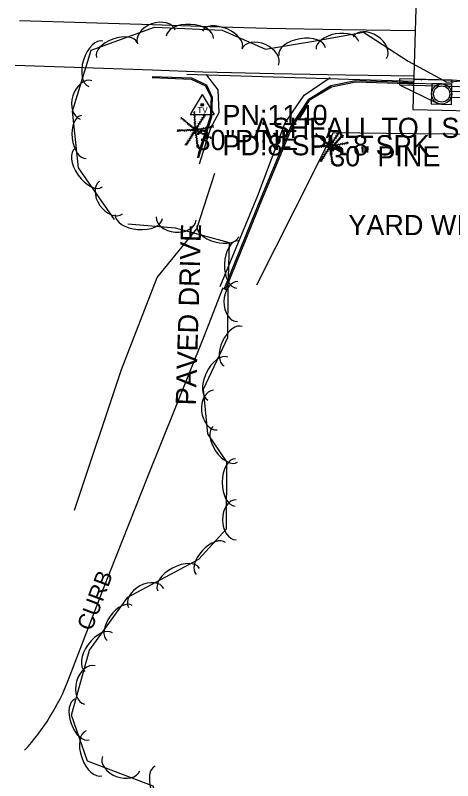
# Model space of a CAD drawing. Extents: x 978516 to 993312, y 1836504 to 1846212.
# Drawn here: x 992339 to 992447.3, y 1840498 to 1840687.6 of the extents above; entities that cross this region are included whole.
import ezdxf

# ---------------------------------------------------------------- set-up
doc = ezdxf.new("R2010")
doc.units = 0
for name, color, linetype in [('R_Drainage', 7, 'Continuous'), ('R_Proposed Road', 7, 'Continuous'), ('S_CURB', 7, 'Continuous'), ('S_CURB_ANNOT', 7, 'Continuous'), ('S_DRIVEWAY', 7, 'Continuous'), ('S_DRIVEWAY_ANNOT', 7, 'Continuous'), ('S_EDGE_PAVEMENT', 7, 'Continuous'), ('S_PARKING', 7, 'Continuous'), ('S_PAVEMENT_CROWN', 7, 'Continuous'), ('S_SECONDARY_CTL', 7, 'Continuous'), ('S_SECONDARY_CTL_ANNOT', 7, 'Continuous'), ('S_SURVEY_TEXT_ANNOT', 7, 'Continuous'), ('S_TREE', 7, 'Continuous'), ('S_TREE_ANNOT', 7, 'Continuous')]:
    doc.layers.add(name, color=color, linetype=linetype)

msp = doc.modelspace()

# ---------------------------------------------------------------- linework, layer by layer
at = {"layer": 'R_Drainage'}
for p, q in [((992434.08, 1840670.38), (992443.43, 1840665.84)), ((992434.1, 1840670.88), (992447.09, 1840670.52)), ((992446.4, 1840668.79), (992530.67, 1840666.48)), ((992446.36, 1840667.29), (992530.63, 1840664.99)), ((992441.96, 1840665.66), (992446.96, 1840665.52))]:
    msp.add_line(p, q, dxfattribs=at)
for points in [[(992434.08, 1840670.38), (992447.08, 1840670.02), (992447.12, 1840671.52), (992434.12, 1840671.88)], [(992441.96, 1840665.66), (992446.96, 1840665.52), (992447.09, 1840670.52), (992442.09, 1840670.66)]]:
    msp.add_lwpolyline(points, close=True, dxfattribs=at)
for radius in [2.5, 2.5, 2.5, 2, 2, 2]:
    msp.add_circle((992444.53, 1840668.09), radius, dxfattribs=at)
at = {"layer": 'R_Proposed Road'}
for p, q in [((992438.54, 1840704.81), (992437.43, 1840664.28)), ((992437.59, 1840670.28), (992673.06, 1840663.85)), ((992437.63, 1840671.78), (992673.1, 1840665.35)), ((992437.43, 1840664.28), (992619.94, 1840659.29))]:
    msp.add_line(p, q, dxfattribs=at)
at = {"layer": 'S_CURB'}
for points in [[(992372.87, 1840672.14), (992382.52, 1840671.78), (992386.08, 1840670.11), (992387.44, 1840667.24), (992387.22, 1840662.39), (992384.35, 1840653.51), (992384.09, 1840652.31)], [(992372.88, 1840672.44), (992382.59, 1840672.08), (992386.3, 1840670.34), (992387.74, 1840667.31), (992387.52, 1840662.34), (992384.64, 1840653.44), (992384.38, 1840652.24)], [(992437.61, 1840670.88), (992436.21, 1840670.93), (992423.24, 1840671.35), (992417.14, 1840670.09), (992411.51, 1840666.66), (992407.23, 1840660.12), (992399.97, 1840642.66), (992390.64, 1840619.62)], [(992437.6, 1840670.58), (992436.2, 1840670.63), (992423.27, 1840671.05), (992417.25, 1840669.81), (992411.72, 1840666.44), (992407.49, 1840659.98), (992400.25, 1840642.54), (992390.92, 1840619.5)]]:
    msp.add_lwpolyline(points, dxfattribs=at)
at = {"layer": 'S_DRIVEWAY'}
for points in [[(992384.59, 1840650.82), (992387.38, 1840659.73), (992389.49, 1840663.5), (992389.21, 1840669.14), (992386.43, 1840672.74)], [(992389.72, 1840620.38), (992399.02, 1840642.94), (992405.76, 1840660.91), (992410.54, 1840667.8), (992416.9, 1840672.15)]]:
    msp.add_lwpolyline(points, dxfattribs=at)
at = {"layer": 'S_EDGE_PAVEMENT'}
for points in [[(992339, 1840675.26), (992355.97, 1840674.67), (992372.95, 1840674.08), (992385.44, 1840673.55), (992403.08, 1840673.17), (992420.71, 1840672.8), (992437.65, 1840672.55)], [(992381.49, 1840672.98), (992437.62, 1840671.3)]]:
    msp.add_lwpolyline(points, dxfattribs=at)
at = {"layer": 'S_PARKING'}
for points in [[(992353.64, 1840564.98), (992365.32, 1840599.8), (992374.07, 1840622.61), (992383.91, 1840634.69), (992388.41, 1840648.48)], [(992352.18, 1840523.01), (992360.81, 1840545.57), (992371.83, 1840573.37), (992385.7, 1840607.87), (992390.48, 1840620.12)]]:
    msp.add_lwpolyline(points, dxfattribs=at)
msp.add_ellipse((992301.38, 1840541.99), major_axis=(35.02, 43.34), ratio=0.97052, start_param=4.653541, end_param=5.025621, dxfattribs=at)
at = {"layer": 'S_PAVEMENT_CROWN'}
msp.add_lwpolyline([(992340.02, 1840686.27), (992356.48, 1840685.77), (992372.94, 1840685.27), (992387.13, 1840684.83), (992401.32, 1840684.39), (992419.74, 1840684.1), (992437.96, 1840683.81)], dxfattribs=at)
at = {"layer": 'S_SECONDARY_CTL'}
for p, q in [((992385.27, 1840668), (992382.26, 1840663.04)), ((992385.27, 1840668), (992388.21, 1840663.04)), ((992382.26, 1840663.04), (992388.21, 1840663.04))]:
    msp.add_line(p, q, dxfattribs=at)
for radius in [0.311, 0.183, 0.103]:
    msp.add_circle((992385.27, 1840665.39), radius, dxfattribs=at)
at = {"layer": 'S_TREE'}
for p, q in [((992383.33, 1840663.27), (992383.11, 1840663.47)), ((992383.36, 1840662.71), (992383.14, 1840662.91)), ((992383.59, 1840659.19), (992383.32, 1840663.63)), ((992383.33, 1840663.52), (992383.52, 1840663.75)), ((992383.36, 1840663.04), (992383.55, 1840663.28)), ((992383.39, 1840662.44), (992383.58, 1840662.68)), ((992383.59, 1840659.19), (992385.93, 1840662.88)), ((992385.66, 1840662.5), (992385.57, 1840662.79)), ((992385.79, 1840662.66), (992386.09, 1840662.71)), ((992385.9, 1840662.84), (992385.81, 1840663.13)), ((992380.3, 1840661.94), (992380.01, 1840661.89)), ((992383.59, 1840659.19), (992380.12, 1840662.1)), ((992380.16, 1840662.08), (992380.16, 1840662.38)), ((992380.65, 1840661.66), (992380.35, 1840661.63)), ((992380.48, 1840661.83), (992380.48, 1840662.13)), ((992381.01, 1840661.34), (992380.71, 1840661.31)), ((992380.83, 1840661.54), (992380.83, 1840661.84)), ((992381.47, 1840660.96), (992381.17, 1840660.94)), ((992381.24, 1840661.17), (992381.24, 1840661.47)), ((992381.66, 1840660.84), (992381.66, 1840661.14)), ((992381.98, 1840660.56), (992381.98, 1840660.86)), ((992383.39, 1840662.14), (992383.17, 1840662.33)), ((992383.42, 1840661.48), (992383.19, 1840661.68)), ((992383.46, 1840660.88), (992383.23, 1840661.08)), ((992383.43, 1840661.73), (992383.62, 1840661.97)), ((992383.49, 1840661.17), (992383.68, 1840661.4)), ((992383.51, 1840660.6), (992383.69, 1840660.83)), ((992384.39, 1840660.48), (992384.3, 1840660.76)), ((992384.55, 1840660.69), (992384.85, 1840660.73)), ((992384.69, 1840660.97), (992384.6, 1840661.25)), ((992384.9, 1840661.21), (992385.2, 1840661.25)), ((992385.06, 1840661.54), (992384.98, 1840661.82)), ((992385.23, 1840661.75), (992385.52, 1840661.79)), ((992385.36, 1840662.05), (992385.27, 1840662.34)), ((992385.55, 1840662.24), (992385.84, 1840662.28)), ((992379.22, 1840658.98), (992379.08, 1840658.71)), ((992383.59, 1840659.19), (992379.13, 1840658.98)), ((992379.37, 1840659), (992379.2, 1840659.25)), ((992379.57, 1840659.01), (992379.43, 1840658.74)), ((992379.75, 1840659.03), (992379.59, 1840659.28)), ((992379.91, 1840659.03), (992379.78, 1840658.76)), ((992380.15, 1840659.03), (992379.99, 1840659.28)), ((992380.33, 1840659.04), (992380.19, 1840658.77)), ((992380.55, 1840659.06), (992380.39, 1840659.3)), ((992380.84, 1840659.06), (992380.7, 1840658.8)), ((992381.12, 1840659.07), (992380.95, 1840659.32)), ((992383.59, 1840659.19), (992381.21, 1840655.42)), ((992381.4, 1840659.09), (992381.27, 1840658.82)), ((992381.68, 1840659.11), (992381.51, 1840659.36)), ((992381.83, 1840660.63), (992381.53, 1840660.61)), ((992381.88, 1840659.11), (992381.75, 1840658.84)), ((992382.17, 1840660.37), (992381.87, 1840660.34)), ((992382.15, 1840659.12), (992381.99, 1840659.37)), ((992382.51, 1840660.07), (992382.21, 1840660.05)), ((992382.35, 1840659.13), (992382.22, 1840658.87)), ((992382.35, 1840660.26), (992382.35, 1840660.56)), ((992382.59, 1840659.16), (992382.43, 1840659.41)), ((992382.88, 1840659.77), (992382.58, 1840659.75)), ((992382.81, 1840659.14), (992382.68, 1840658.87)), ((992382.72, 1840659.95), (992382.72, 1840660.25)), ((992382.93, 1840659.2), (992382.76, 1840659.45)), ((992383.24, 1840659.48), (992382.94, 1840659.45)), ((992383.07, 1840659.64), (992383.07, 1840659.94)), ((992383.2, 1840659.15), (992383.07, 1840658.89)), ((992383.5, 1840660.32), (992383.27, 1840660.51)), ((992383.51, 1840659.7), (992383.28, 1840659.9)), ((992383.38, 1840658.87), (992383.46, 1840658.58)), ((992383.53, 1840659.93), (992383.72, 1840660.16)), ((992383.59, 1840659.19), (992388.01, 1840660.06)), ((992383.59, 1840659.19), (992387.5, 1840657.15)), ((992383.59, 1840659.19), (992384.12, 1840654.82)), ((992383.66, 1840658.77), (992383.92, 1840658.61)), ((992383.92, 1840659.01), (992384.18, 1840659.15)), ((992384.03, 1840659.95), (992383.94, 1840660.23)), ((992383.94, 1840659.68), (992384.23, 1840659.73)), ((992383.96, 1840659.28), (992384.17, 1840659.5)), ((992384.1, 1840658.92), (992384.17, 1840658.62)), ((992384.21, 1840659.31), (992384.46, 1840659.15)), ((992384.22, 1840660.15), (992384.52, 1840660.19)), ((992384.36, 1840659.34), (992384.57, 1840659.56)), ((992384.39, 1840658.79), (992384.66, 1840658.93)), ((992384.72, 1840659.39), (992384.98, 1840659.23)), ((992384.89, 1840659.44), (992385.09, 1840659.66)), ((992385.24, 1840659.5), (992385.49, 1840659.34)), ((992385.46, 1840659.57), (992385.66, 1840659.79)), ((992385.84, 1840659.63), (992386.1, 1840659.47)), ((992386.09, 1840659.71), (992386.29, 1840659.93)), ((992386.43, 1840659.73), (992386.68, 1840659.57)), ((992386.69, 1840659.8), (992386.89, 1840660.02)), ((992386.94, 1840659.85), (992387.19, 1840659.69)), ((992387.17, 1840659.9), (992387.37, 1840660.13)), ((992387.36, 1840659.94), (992387.61, 1840659.78)), ((992387.62, 1840659.99), (992387.82, 1840660.22)), ((992387.77, 1840660), (992388.02, 1840659.84)), ((992387.84, 1840660.05), (992388.04, 1840660.27)), ((992416.69, 1840659.24), (992416.46, 1840659.44)), ((992416.72, 1840658.68), (992416.5, 1840658.88)), ((992416.94, 1840655.16), (992416.67, 1840659.6)), ((992416.69, 1840659.49), (992416.87, 1840659.72)), ((992416.71, 1840659.01), (992416.9, 1840659.24)), ((992416.94, 1840655.16), (992419.29, 1840658.84)), ((992419.26, 1840658.81), (992419.17, 1840659.1)), ((992382.23, 1840657.04), (992381.93, 1840657.01)), ((992382.49, 1840657.46), (992382.19, 1840657.43)), ((992382.37, 1840657.26), (992382.45, 1840656.97)), ((992382.74, 1840657.88), (992382.44, 1840657.85)), ((992382.63, 1840657.68), (992382.71, 1840657.39)), ((992383.02, 1840658.33), (992382.72, 1840658.29)), ((992382.89, 1840658.1), (992382.97, 1840657.81)), ((992383.26, 1840658.7), (992382.96, 1840658.66)), ((992383.17, 1840658.53), (992383.24, 1840658.24)), ((992383.65, 1840658.52), (992383.45, 1840658.29)), ((992383.71, 1840657.94), (992383.52, 1840657.71)), ((992383.8, 1840657.38), (992383.6, 1840657.15)), ((992383.7, 1840658.21), (992383.96, 1840658.06)), ((992383.79, 1840657.64), (992384.04, 1840657.49)), ((992383.85, 1840657.1), (992384.11, 1840656.94)), ((992384.68, 1840658.61), (992384.75, 1840658.32)), ((992384.95, 1840658.48), (992385.21, 1840658.62)), ((992385.21, 1840658.33), (992385.28, 1840658.04)), ((992385.5, 1840658.2), (992385.77, 1840658.34)), ((992385.74, 1840658.06), (992385.81, 1840657.77)), ((992385.99, 1840657.94), (992386.25, 1840658.08)), ((992386.27, 1840657.77), (992386.34, 1840657.48)), ((992386.52, 1840657.67), (992386.79, 1840657.81)), ((992386.79, 1840657.51), (992386.86, 1840657.22)), ((992387.07, 1840657.39), (992387.34, 1840657.53)), ((992387.28, 1840657.26), (992387.35, 1840656.97)), ((992387.46, 1840657.19), (992387.73, 1840657.33)), ((992413.66, 1840657.9), (992413.36, 1840657.86)), ((992416.94, 1840655.16), (992413.48, 1840658.07)), ((992413.52, 1840658.04), (992413.52, 1840658.34)), ((992414.01, 1840657.63), (992413.71, 1840657.6)), ((992413.83, 1840657.79), (992413.83, 1840658.09)), ((992414.37, 1840657.3), (992414.07, 1840657.28)), ((992414.19, 1840657.5), (992414.19, 1840657.8)), ((992414.83, 1840656.93), (992414.53, 1840656.9)), ((992414.6, 1840657.14), (992414.6, 1840657.44)), ((992415.01, 1840656.81), (992415.01, 1840657.11)), ((992416.75, 1840658.1), (992416.52, 1840658.3)), ((992416.78, 1840657.44), (992416.55, 1840657.64)), ((992416.81, 1840656.85), (992416.59, 1840657.05)), ((992416.75, 1840658.41), (992416.93, 1840658.64)), ((992416.79, 1840657.7), (992416.97, 1840657.93)), ((992416.85, 1840657.13), (992417.04, 1840657.37)), ((992418.05, 1840656.93), (992417.96, 1840657.22)), ((992418.26, 1840657.17), (992418.56, 1840657.22)), ((992418.42, 1840657.5), (992418.33, 1840657.79)), ((992418.58, 1840657.72), (992418.88, 1840657.76)), ((992418.72, 1840658.02), (992418.63, 1840658.31)), ((992418.9, 1840658.21), (992419.2, 1840658.25)), ((992419.01, 1840658.47), (992418.92, 1840658.76)), ((992419.15, 1840658.63), (992419.45, 1840658.68)), ((992381.24, 1840655.5), (992380.94, 1840655.47)), ((992381.44, 1840655.81), (992381.14, 1840655.77)), ((992381.36, 1840655.66), (992381.44, 1840655.37)), ((992381.69, 1840656.22), (992381.39, 1840656.19)), ((992381.59, 1840656.01), (992381.66, 1840655.72)), ((992381.93, 1840656.59), (992381.63, 1840656.56)), ((992381.84, 1840656.41), (992381.92, 1840656.12)), ((992382.09, 1840656.79), (992382.17, 1840656.5)), ((992383.87, 1840656.81), (992383.67, 1840656.58)), ((992383.93, 1840656.35), (992383.74, 1840656.12)), ((992383.97, 1840655.97), (992383.78, 1840655.74)), ((992384.03, 1840655.52), (992383.83, 1840655.3)), ((992384.07, 1840655.1), (992383.88, 1840654.88)), ((992383.92, 1840656.59), (992384.18, 1840656.43)), ((992383.95, 1840656.15), (992384.21, 1840656)), ((992384, 1840655.75), (992384.26, 1840655.59)), ((992384.06, 1840655.28), (992384.32, 1840655.13)), ((992416.94, 1840655.16), (992412.49, 1840654.95)), ((992412.72, 1840654.97), (992412.56, 1840655.22)), ((992412.92, 1840654.97), (992412.79, 1840654.71)), ((992413.11, 1840655), (992412.94, 1840655.25)), ((992413.27, 1840654.99), (992413.13, 1840654.72)), ((992413.51, 1840655), (992413.34, 1840655.25)), ((992413.68, 1840655.01), (992413.55, 1840654.74)), ((992413.91, 1840655.02), (992413.74, 1840655.27)), ((992414.19, 1840655.03), (992414.06, 1840654.76)), ((992414.48, 1840655.04), (992414.31, 1840655.28)), ((992416.94, 1840655.16), (992414.56, 1840651.39)), ((992414.76, 1840655.06), (992414.62, 1840654.79)), ((992415.03, 1840655.07), (992414.87, 1840655.32)), ((992415.19, 1840656.6), (992414.89, 1840656.58)), ((992415.24, 1840655.08), (992415.11, 1840654.81)), ((992415.52, 1840656.33), (992415.22, 1840656.31)), ((992415.34, 1840656.53), (992415.34, 1840656.83)), ((992415.51, 1840655.09), (992415.34, 1840655.34)), ((992415.87, 1840656.04), (992415.57, 1840656.01)), ((992415.71, 1840655.1), (992415.58, 1840654.83)), ((992415.7, 1840656.23), (992415.7, 1840656.53)), ((992415.95, 1840655.13), (992415.78, 1840655.37)), ((992416.23, 1840655.74), (992415.93, 1840655.72)), ((992416.17, 1840655.11), (992416.03, 1840654.84)), ((992416.07, 1840655.92), (992416.07, 1840656.22)), ((992416.29, 1840655.16), (992416.12, 1840655.41)), ((992416.59, 1840655.44), (992416.3, 1840655.42)), ((992416.56, 1840655.12), (992416.42, 1840654.85)), ((992416.43, 1840655.61), (992416.43, 1840655.91)), ((992416.85, 1840656.28), (992416.63, 1840656.48)), ((992416.87, 1840655.66), (992416.64, 1840655.86)), ((992416.86, 1840656.57), (992417.05, 1840656.8)), ((992416.89, 1840655.89), (992417.08, 1840656.13)), ((992416.94, 1840655.16), (992421.36, 1840656.03)), ((992416.94, 1840655.16), (992420.86, 1840653.12)), ((992416.94, 1840655.16), (992417.47, 1840650.79)), ((992417.27, 1840654.98), (992417.54, 1840655.12)), ((992417.29, 1840655.65), (992417.59, 1840655.69)), ((992417.39, 1840655.92), (992417.3, 1840656.2)), ((992417.32, 1840655.25), (992417.52, 1840655.47)), ((992417.56, 1840655.28), (992417.82, 1840655.12)), ((992417.58, 1840656.12), (992417.87, 1840656.16)), ((992417.75, 1840656.44), (992417.66, 1840656.73)), ((992417.72, 1840655.3), (992417.92, 1840655.53)), ((992417.91, 1840656.66), (992418.21, 1840656.7)), ((992418.08, 1840655.35), (992418.33, 1840655.19)), ((992418.25, 1840655.41), (992418.45, 1840655.63)), ((992418.59, 1840655.47), (992418.85, 1840655.31)), ((992418.82, 1840655.54), (992419.02, 1840655.76)), ((992419.2, 1840655.6), (992419.45, 1840655.44)), ((992419.45, 1840655.68), (992419.65, 1840655.9)), ((992419.78, 1840655.7), (992420.04, 1840655.54)), ((992420.04, 1840655.77), (992420.24, 1840655.99)), ((992420.29, 1840655.82), (992420.54, 1840655.66)), ((992420.53, 1840655.87), (992420.73, 1840656.09)), ((992420.72, 1840655.91), (992420.97, 1840655.75)), ((992420.97, 1840655.96), (992421.17, 1840656.18)), ((992421.12, 1840655.97), (992421.38, 1840655.81)), ((992421.2, 1840656.01), (992421.4, 1840656.24)), ((992384.1, 1840654.94), (992384.36, 1840654.79)), ((992412.58, 1840654.95), (992412.44, 1840654.68)), ((992415.85, 1840653.43), (992415.55, 1840653.4)), ((992415.73, 1840653.23), (992415.81, 1840652.93)), ((992416.1, 1840653.85), (992415.8, 1840653.82)), ((992415.99, 1840653.65), (992416.06, 1840653.36)), ((992416.38, 1840654.3), (992416.08, 1840654.26)), ((992416.25, 1840654.06), (992416.32, 1840653.77)), ((992416.61, 1840654.66), (992416.32, 1840654.63)), ((992416.52, 1840654.5), (992416.6, 1840654.21)), ((992416.74, 1840654.84), (992416.81, 1840654.55)), ((992417, 1840654.48), (992416.81, 1840654.26)), ((992417.07, 1840653.9), (992416.87, 1840653.68)), ((992417.15, 1840653.34), (992416.96, 1840653.12)), ((992417.02, 1840654.73), (992417.28, 1840654.58)), ((992417.06, 1840654.18), (992417.32, 1840654.02)), ((992417.14, 1840653.61), (992417.4, 1840653.46)), ((992417.45, 1840654.88), (992417.52, 1840654.59)), ((992417.75, 1840654.75), (992418.01, 1840654.89)), ((992418.03, 1840654.58), (992418.1, 1840654.29)), ((992418.3, 1840654.45), (992418.57, 1840654.59)), ((992418.57, 1840654.3), (992418.64, 1840654.01)), ((992418.86, 1840654.17), (992419.12, 1840654.31)), ((992419.09, 1840654.03), (992419.16, 1840653.74)), ((992419.34, 1840653.91), (992419.61, 1840654.05)), ((992419.63, 1840653.73), (992419.7, 1840653.44)), ((992419.88, 1840653.64), (992420.14, 1840653.78)), ((992420.14, 1840653.48), (992420.21, 1840653.19)), ((992420.43, 1840653.36), (992420.69, 1840653.5)), ((992420.63, 1840653.23), (992420.7, 1840652.93)), ((992420.82, 1840653.15), (992421.09, 1840653.29)), ((992414.59, 1840651.47), (992414.3, 1840651.44)), ((992414.79, 1840651.77), (992414.5, 1840651.74)), ((992414.72, 1840651.63), (992414.79, 1840651.34)), ((992415.05, 1840652.19), (992414.75, 1840652.15)), ((992414.94, 1840651.98), (992415.02, 1840651.69)), ((992415.28, 1840652.56), (992414.99, 1840652.53)), ((992415.2, 1840652.38), (992415.28, 1840652.09)), ((992415.58, 1840653.01), (992415.28, 1840652.98)), ((992415.45, 1840652.76), (992415.52, 1840652.47)), ((992417.22, 1840652.77), (992417.03, 1840652.55)), ((992417.29, 1840652.32), (992417.09, 1840652.09)), ((992417.33, 1840651.94), (992417.13, 1840651.71)), ((992417.39, 1840651.49), (992417.19, 1840651.26)), ((992417.21, 1840653.06), (992417.46, 1840652.91)), ((992417.28, 1840652.55), (992417.53, 1840652.4)), ((992417.31, 1840652.12), (992417.57, 1840651.97)), ((992417.36, 1840651.72), (992417.61, 1840651.56)), ((992417.42, 1840651.25), (992417.68, 1840651.09)), ((992417.43, 1840651.07), (992417.23, 1840650.84)), ((992417.46, 1840650.91), (992417.72, 1840650.75))]:
    msp.add_line(p, q, dxfattribs=at)
for points in [[(992363.58, 1840637), (992354.65, 1840649.76), (992353.12, 1840663.84), (992357.78, 1840678.93), (992373.46, 1840684.62), (992390.21, 1840683.88), (992400.91, 1840679.23), (992412.34, 1840681.12), (992425.21, 1840683.41), (992436.22, 1840676.25), (992445.82, 1840670.99), (992459.51, 1840672.34), (992463.83, 1840671.06)], [(992458.94, 1840617.76), (992458.02, 1840637.91), (992457.09, 1840658.06), (992437.39, 1840658.24), (992417.69, 1840658.43), (992408.18, 1840639.58), (992398.68, 1840620.74)], [(992381.29, 1840474.11), (992373.16, 1840496.61), (992356.9, 1840502.84), (992352.89, 1840514.25), (992357.37, 1840530.29), (992366.85, 1840543.48), (992384.41, 1840552.86), (992391.26, 1840560.38), (992391.35, 1840576.95), (992386.67, 1840583.87), (992385.61, 1840594.99), (992391.6, 1840607.8), (992391.68, 1840619.66), (992392.02, 1840631.23), (992378.69, 1840634.87), (992366.85, 1840635.82)]]:
    msp.add_lwpolyline(points, dxfattribs=at)
for centre, major_axis, ratio, start_param, end_param in [((992373.9, 1840682.24), (-4.66, -1.69), 0.685308, 3.141593, 6.283185), ((992382.22, 1840682.11), (-5.86, 0.26), 0.550077, 3.141593, 6.283185), ((992390.25, 1840681.55), (-4.9, 2.13), 0.540697, 3.141593, 6.283185), ((992418.76, 1840680.11), (-5.26, -0.94), 0.540697, 3.141593, 6.283185), ((992426.74, 1840679.58), (-4.15, 2.7), 0.685308, 3.141593, 6.283185), ((992358.95, 1840675.55), (-1.73, -5.61), 0.55008, 3.141593, 6.283185), ((992364.12, 1840678.98), (-5.03, -1.82), 0.540697, 3.141593, 6.283185), ((992410, 1840678.58), (-5.79, -0.96), 0.550077, 3.141593, 6.283185), ((992399.59, 1840677.2), (-4.54, 1.98), 0.685307, 3.141593, 6.283185), ((992356.48, 1840666.63), (-1.46, -4.74), 0.685311, 3.141593, 6.283185), ((992434.64, 1840674.75), (-4.92, 3.2), 0.550077, 3.141593, 3.203077), ((992355.95, 1840657.45), (0.58, -5.32), 0.540699, 3.141593, 6.283185), ((992357.18, 1840649.86), (3.36, -4.81), 0.550078, 3.141593, 6.283185), ((992362.7, 1840642.42), (2.84, -4.06), 0.685309, 3.141593, 6.283185), ((992369.58, 1840637.73), (5.85, -0.46), 0.550079, 3.141593, 6.283185), ((992378.83, 1840637.25), (4.94, -0.39), 0.68531, 3.141593, 6.283185), ((992389.14, 1840634.22), (5.16, -1.41), 0.540696, 3.141593, 6.283185), ((992393.98, 1840625.87), (-0.17, -5.87), 0.549927, 3.141593, 6.283185), ((992394.04, 1840616.66), (-0.03, -4.96), 0.685121, 3.141593, 6.283185), ((992392.92, 1840605.61), (-2.26, -4.84), 0.540563, 3.141593, 6.283185), ((992389.16, 1840597.57), (-2.48, -5.32), 0.549941, 3.141593, 6.283185), ((992388.5, 1840589.82), (0.47, -4.93), 0.685127, 3.141593, 6.283185), ((992390.98, 1840581.29), (3, -4.43), 0.540612, 3.141593, 6.283185), ((992393.45, 1840571.88), (-0.03, -5.87), 0.549927, 3.141593, 6.283185), ((992393.66, 1840562.62), (-0.03, -4.96), 0.685121, 3.141593, 6.283185), ((992387.4, 1840553), (-3.6, -3.95), 0.5406, 3.141593, 6.283185), ((992379.45, 1840547.81), (-5.18, -2.77), 0.55003, 3.141593, 6.283185), ((992371.41, 1840543.22), (-4.37, -2.34), 0.685248, 3.141593, 6.283185), ((992364.83, 1840537.04), (-3.12, -4.34), 0.540584, 3.141593, 6.283185), ((992359.66, 1840529.84), (-3.42, -4.77), 0.549962, 3.141593, 6.283185), ((992357.43, 1840521.67), (-1.33, -4.77), 0.685123, 3.141593, 6.283185), ((992355.53, 1840513.13), (1.77, -5.04), 0.540577, 3.141593, 6.283185), ((992358.47, 1840504.76), (1.95, -5.54), 0.549955, 3.141593, 6.283185), ((992365.19, 1840502.21), (4.63, -1.77), 0.685299, 3.141593, 6.283185), ((992375.44, 1840496.53), (1.81, -5.03), 0.540862, 3.142119, 6.283711)]:
    msp.add_ellipse(centre, major_axis=major_axis, ratio=ratio, start_param=start_param, end_param=end_param, dxfattribs=at)

# ---------------------------------------------------------------- texts
at = {"layer": 'S_CURB_ANNOT'}
msp.add_text('CURB', height=4, rotation=69.4891, dxfattribs=at).set_placement((992357.89, 1840534.86))
at = {"layer": 'S_DRIVEWAY_ANNOT'}
msp.add_text('PAVED DRIVE', height=5.0005, rotation=88.2942, dxfattribs=at).set_placement((992383.68, 1840590.89))
at = {"layer": 'S_SECONDARY_CTL'}
msp.add_text('TV', height=1.5, dxfattribs=at).set_placement((992384.06, 1840663.38))
at = {"layer": 'S_SECONDARY_CTL_ANNOT'}
for s, p in [('PN:1140', (992390.27, 1840660.39)), ('PD:8-SPK 8 SPK', (992390.27, 1840652.89))]:
    msp.add_text(s, height=5, dxfattribs=at).set_placement(p)
at = {"layer": 'S_SURVEY_TEXT_ANNOT'}
for s, p in [('ASHFALL TO I STORY FRAME/', (992398.01, 1840657.2)), ('YARD WITH SCATTERED', (992421.43, 1840633.12))]:
    msp.add_text(s, height=5, dxfattribs=at).set_placement(p)
at = {"layer": 'S_TREE_ANNOT'}
for s, p in [('30"PINE', (992383.59, 1840654.19)), ('30" PINE', (992416.94, 1840650.16))]:
    msp.add_text(s, height=5, dxfattribs=at).set_placement(p)

doc.saveas('drawing.dxf')
